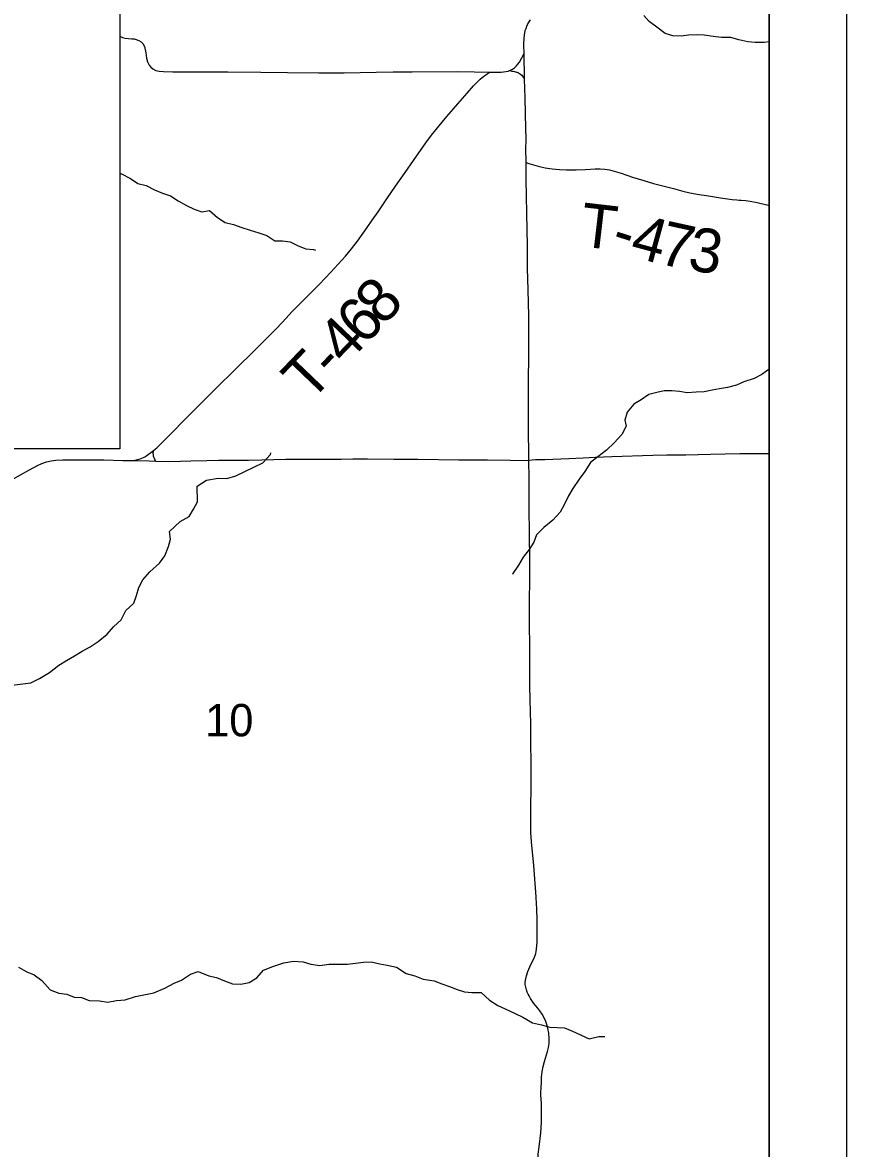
# Model space of a CAD drawing. Extents: x -7.5 to 53.5, y 0 to 22.
# Drawn here: x 7.935 to 9, y 15.27 to 16.725 of the extents above; entities that cross this region are included whole.
import ezdxf

# ---------------------------------------------------------------- set-up
doc = ezdxf.new("R2010")
doc.units = 0
for name, color, linetype in [('GM_X_Corporation', 7, 'Continuous'), ('GM_X_Minor_River', 7, 'Continuous'), ('GM_X_Section_Text', 7, 'Continuous'), ('GM_X_Township_Road', 7, 'Continuous'), ('GM_X_Township_Road_Text', 7, 'Continuous'), ('SH_Data', 7, 'Continuous'), ('SH_Text', 7, 'Continuous')]:
    doc.layers.add(name, color=color, linetype=linetype)

msp = doc.modelspace()

# ---------------------------------------------------------------- linework, layer by layer
at = {"layer": 'GM_X_Corporation'}
msp.add_lwpolyline([(8.9, 14.1), (8.9, 19.1887), (8.5159, 19.1718), (8.414, 19.1709), (7.544, 19.1455), (6.5522, 19.1561), (6.0433, 19.1527), (6.0424, 19.1527), (5.0411, 19.1401), (4.5565, 19.1354), (4.5696, 18.2604), (4.5718, 18.1276), (4.5771, 17.6201), (4.5749, 17.2575), (4.577, 17.1178), (4.5822, 16.8992), (4.5826, 16.8462), (4.5872, 16.3635), (4.5873, 16.3533), (4.594, 15.8096), (4.6021, 15.6139), (4.6087, 14.5302)], dxfattribs=at)
at = {"layer": 'GM_X_Minor_River'}
for points in [[(8.9, 16.7003), (8.8936, 16.6998), (8.8822, 16.6996), (8.8724, 16.7004), (8.861, 16.7032), (8.8504, 16.7059), (8.8387, 16.706), (8.8277, 16.7076), (8.8163, 16.7093), (8.8065, 16.7097), (8.7959, 16.7091), (8.7864, 16.708), (8.7754, 16.7081), (8.7656, 16.7112), (8.755, 16.7193), (8.7452, 16.7266), (8.738, 16.7346)], [(8.061, 16.53), (8.0633, 16.5299), (8.0746, 16.5237), (8.0844, 16.5172), (8.095, 16.5148), (8.1059, 16.5094), (8.1161, 16.5051), (8.1263, 16.5016), (8.1365, 16.4951), (8.1471, 16.4889), (8.1569, 16.4843), (8.1671, 16.4808), (8.1769, 16.4826), (8.1871, 16.4734), (8.1973, 16.4672), (8.2079, 16.4645), (8.2185, 16.4606), (8.2294, 16.4571), (8.2404, 16.4536), (8.251, 16.4501), (8.2615, 16.4435), (8.271, 16.4434), (8.2812, 16.4422), (8.2914, 16.4368), (8.3012, 16.4329), (8.3111, 16.4321), (8.3137, 16.4313)], [(8.9, 16.2775), (8.8908, 16.2706), (8.8805, 16.2654), (8.8672, 16.2613), (8.8577, 16.2569), (8.8463, 16.2539), (8.8361, 16.2521), (8.8266, 16.2503), (8.8159, 16.2481), (8.8057, 16.2478), (8.7943, 16.2468), (8.7841, 16.2488), (8.7743, 16.2496), (8.7644, 16.2494), (8.7549, 16.2472), (8.7446, 16.2446), (8.7347, 16.2379), (8.7252, 16.2323), (8.7168, 16.2221), (8.7137, 16.2115), (8.7155, 16.2038)], [(8.7155, 16.2038), (8.7099, 16.1931), (8.6998, 16.1824), (8.69, 16.1729), (8.6788, 16.164), (8.669, 16.1567), (8.6619, 16.1453), (8.6544, 16.1354), (8.6465, 16.1232), (8.6406, 16.1136), (8.6354, 16.103), (8.6301, 16.0927), (8.6204, 16.0824), (8.6091, 16.0728), (8.5993, 16.0632), (8.596, 16.0537), (8.59, 16.0442), (8.5822, 16.0346), (8.5762, 16.024), (8.5687, 16.0133), (8.5684, 16.0121)], [(7.9217, 15.869), (7.9357, 15.871), (7.9459, 15.8722), (7.9573, 15.8776), (7.9701, 15.8853), (7.9821, 15.8949), (7.9919, 15.9011), (8.0025, 15.9069), (8.0123, 15.913), (8.0228, 15.9184), (8.033, 15.9253), (8.0446, 15.9349), (8.0529, 15.9445), (8.0627, 15.9533), (8.0686, 15.9655), (8.0791, 15.975), (8.0825, 15.9849), (8.0854, 15.9952), (8.0906, 16.0051), (8.0996, 16.0154), (8.1124, 16.0269), (8.1191, 16.0364), (8.1239, 16.0482), (8.1265, 16.0577), (8.1253, 16.0676), (8.1388, 16.0806), (8.1505, 16.0872), (8.1561, 16.0967), (8.1613, 16.1062), (8.1611, 16.1263), (8.1732, 16.134), (8.1879, 16.1368), (8.1993, 16.1361), (8.211, 16.1396), (8.2227, 16.1454), (8.2352, 16.1512), (8.2457, 16.1566), (8.2559, 16.167), (8.2562, 16.1692)], [(7.9299, 15.5045), (7.941, 15.4985), (7.9505, 15.4948), (7.96, 15.4873), (7.9708, 15.4752), (7.9822, 15.4712), (7.9924, 15.4697), (8.0019, 15.466), (8.0114, 15.4653), (8.0213, 15.4616), (8.0349, 15.461), (8.0455, 15.4592), (8.0569, 15.4615), (8.0679, 15.4624), (8.0811, 15.4667), (8.0943, 15.4694), (8.1049, 15.4714), (8.1193, 15.4776), (8.131, 15.4838), (8.1408, 15.488), (8.1521, 15.4957), (8.1623, 15.4992), (8.176, 15.4936), (8.1858, 15.4911), (8.1961, 15.487), (8.2068, 15.4829), (8.2174, 15.4826), (8.2283, 15.4846), (8.2381, 15.4908), (8.2468, 15.5007), (8.2588, 15.5053), (8.2728, 15.5104), (8.2853, 15.5124), (8.2978, 15.5117), (8.3077, 15.5084), (8.3194, 15.5066), (8.3316, 15.5086), (8.3456, 15.5087), (8.3554, 15.5084), (8.3759, 15.5109), (8.3857, 15.5113), (8.3971, 15.5088), (8.4066, 15.5073), (8.4184, 15.5044)], [(8.4184, 15.5044), (8.4309, 15.4965), (8.4423, 15.4932), (8.453, 15.4891), (8.467, 15.487), (8.4773, 15.4829), (8.4868, 15.4796), (8.4967, 15.4758), (8.5062, 15.4729), (8.5157, 15.4718), (8.5278, 15.4719), (8.5389, 15.4618), (8.5495, 15.455), (8.559, 15.4506), (8.572, 15.4446), (8.5819, 15.4398), (8.5941, 15.4326), (8.6058, 15.4301), (8.6165, 15.4271), (8.6263, 15.4265), (8.6358, 15.4262), (8.6461, 15.4217), (8.6674, 15.412), (8.6799, 15.4148), (8.6878, 15.4152)]]:
    msp.add_lwpolyline(points, dxfattribs=at)
at = {"layer": 'GM_X_Township_Road'}
msp.add_line((8.5841, 16.6521), (8.5833, 16.6853), dxfattribs=at)
for points in [[(8.5833, 16.6853), (8.5831, 16.6965), (8.5834, 16.7058), (8.5842, 16.712), (8.5849, 16.715), (8.5859, 16.7179), (8.587, 16.7208), (8.5883, 16.7236), (8.5898, 16.7264), (8.5915, 16.7289)], [(8.061, 16.7079), (8.0644, 16.706), (8.0677, 16.7053), (8.0764, 16.7044), (8.0793, 16.7042), (8.0822, 16.7035), (8.0856, 16.7024), (8.0887, 16.7007), (8.0909, 16.6982), (8.0928, 16.6944), (8.0945, 16.6865), (8.0953, 16.6794), (8.0966, 16.6745), (8.0987, 16.6704), (8.101, 16.6677), (8.1036, 16.6657), (8.1077, 16.6635), (8.1119, 16.6624), (8.1176, 16.6621), (8.1296, 16.6619), (8.134, 16.6619), (8.1421, 16.6616), (8.1603, 16.6616), (8.179, 16.6616), (8.2005, 16.6616), (8.2434, 16.6614), (8.2778, 16.6607), (8.3181, 16.6605), (8.351, 16.6606), (8.3924, 16.6613), (8.4141, 16.6617), (8.4389, 16.6618), (8.4978, 16.6622), (8.5195, 16.6618), (8.5385, 16.6614)], [(8.5645, 16.6633), (8.5657, 16.6637), (8.5684, 16.6653), (8.571, 16.6669), (8.5733, 16.669), (8.5776, 16.6741), (8.5833, 16.6853)], [(8.5385, 16.6614), (8.5473, 16.6612), (8.5536, 16.6613), (8.5597, 16.662), (8.5628, 16.6627), (8.5645, 16.6633)], [(8.5645, 16.6633), (8.5662, 16.663), (8.5677, 16.6628), (8.5694, 16.6625), (8.5709, 16.6623), (8.5724, 16.6619), (8.5735, 16.6615), (8.5745, 16.6611), (8.5761, 16.6604), (8.5776, 16.6595), (8.5788, 16.6587), (8.5804, 16.6575), (8.5841, 16.6521)], [(8.3871, 16.4699), (8.3948, 16.4809), (8.4069, 16.4987), (8.4174, 16.514), (8.4299, 16.5318), (8.4403, 16.5472), (8.4563, 16.57), (8.4638, 16.5798), (8.4715, 16.5895), (8.4835, 16.6038), (8.4977, 16.6202), (8.5097, 16.6343), (8.5179, 16.6436), (8.5222, 16.648), (8.5267, 16.6523), (8.5315, 16.6562), (8.5339, 16.658), (8.5385, 16.6614)], [(8.586, 16.5444), (8.5858, 16.5631), (8.5859, 16.5724), (8.5859, 16.5754), (8.5856, 16.5879), (8.5846, 16.6282), (8.5841, 16.6521)], [(8.5897, 16.1599), (8.5897, 16.1614), (8.5893, 16.2035), (8.5891, 16.2221), (8.5889, 16.2407), (8.5891, 16.2637), (8.5894, 16.2935), (8.5894, 16.3173), (8.5894, 16.3326), (8.5895, 16.3462), (8.5887, 16.3802), (8.588, 16.4081), (8.5878, 16.4243), (8.5876, 16.4375), (8.5873, 16.4577), (8.5869, 16.4794), (8.5865, 16.5011), (8.5862, 16.5228), (8.586, 16.5444)], [(8.586, 16.5444), (8.5897, 16.5433), (8.5927, 16.5424), (8.6016, 16.5399), (8.6106, 16.5378), (8.6198, 16.5362), (8.629, 16.5353), (8.6382, 16.5349), (8.6506, 16.535), (8.6629, 16.5357), (8.6753, 16.5364), (8.6815, 16.5364), (8.6877, 16.536), (8.6938, 16.535), (8.6999, 16.5335), (8.7087, 16.5306), (8.7234, 16.5255), (8.7383, 16.5211), (8.7506, 16.5176), (8.7766, 16.5108), (8.7885, 16.5076), (8.7975, 16.5055), (8.8097, 16.5033), (8.8189, 16.5017), (8.8372, 16.4988), (8.8463, 16.4975), (8.8524, 16.4968), (8.8583, 16.4962), (8.8613, 16.4959), (8.8641, 16.4957), (8.8697, 16.4953), (8.8757, 16.4944), (8.8848, 16.4927), (8.8969, 16.49), (8.9, 16.4891)], [(8.1047, 16.1723), (8.1087, 16.1759), (8.1201, 16.1869), (8.1527, 16.2201), (8.1702, 16.2377), (8.1834, 16.2508), (8.2122, 16.2791), (8.2343, 16.3008), (8.252, 16.3182), (8.2627, 16.3293), (8.2712, 16.3382), (8.2753, 16.3428), (8.2838, 16.3519), (8.2902, 16.3586), (8.3035, 16.3717), (8.3188, 16.3871), (8.3337, 16.4029), (8.3524, 16.4236), (8.3604, 16.4331), (8.368, 16.4429), (8.3806, 16.4606), (8.3871, 16.4699)], [(8.0797, 16.1593), (8.084, 16.1605), (8.0871, 16.1616), (8.0914, 16.1634), (8.0942, 16.1648), (8.0965, 16.1663), (8.1011, 16.1697), (8.1047, 16.1723)], [(8.1075, 16.1587), (8.1064, 16.1606), (8.1057, 16.1621), (8.1051, 16.1636), (8.1047, 16.1651), (8.1043, 16.1669), (8.1041, 16.1688), (8.1041, 16.1699), (8.1043, 16.1708), (8.1045, 16.1716), (8.1047, 16.1723)], [(8.5897, 16.1599), (8.598, 16.1607), (8.6103, 16.1609), (8.6413, 16.1621), (8.6598, 16.163), (8.6753, 16.1637), (8.6968, 16.1647), (8.7496, 16.1665), (8.7679, 16.1668), (8.7925, 16.1669), (8.8244, 16.1678), (8.8624, 16.1683), (8.9, 16.1684)], [(7.9218, 16.1349), (7.9432, 16.147), (7.9545, 16.1531), (7.9602, 16.1555), (7.9661, 16.1575), (7.9721, 16.1589), (7.9782, 16.1598), (7.9873, 16.1603), (8.0153, 16.1604), (8.0405, 16.1602), (8.0648, 16.1596), (8.0797, 16.1593)], [(8.0797, 16.1593), (8.0989, 16.159), (8.1075, 16.1587)], [(8.1075, 16.1587), (8.1237, 16.1582), (8.1392, 16.1584), (8.1526, 16.1588), (8.1733, 16.1595), (8.1888, 16.1597), (8.2043, 16.1597), (8.2272, 16.1598), (8.2446, 16.1602), (8.2601, 16.1607), (8.2755, 16.1612), (8.2942, 16.1613), (8.322, 16.1611), (8.3468, 16.1613), (8.3623, 16.1614), (8.3809, 16.1615), (8.4151, 16.1612), (8.4461, 16.161), (8.4989, 16.1604), (8.5362, 16.1604), (8.5653, 16.1598), (8.5865, 16.1596), (8.5897, 16.1599)], [(8.606, 15.3097), (8.606, 15.3137), (8.6058, 15.3286), (8.6052, 15.3396), (8.6052, 15.3428), (8.6054, 15.3487), (8.6057, 15.3558), (8.6061, 15.3626), (8.6067, 15.3692), (8.6081, 15.3762), (8.6096, 15.3829), (8.6137, 15.3957), (8.6149, 15.4009), (8.6157, 15.4061), (8.6158, 15.4125), (8.6155, 15.4191), (8.6142, 15.4253), (8.6131, 15.4294), (8.6115, 15.4346), (8.6093, 15.4392), (8.6067, 15.4437), (8.6036, 15.448), (8.6011, 15.4515), (8.596, 15.4576), (8.5917, 15.4641), (8.5898, 15.4675), (8.5886, 15.4697), (8.5875, 15.4725), (8.5866, 15.4755), (8.5858, 15.4788), (8.585, 15.4822), (8.5849, 15.4851), (8.5855, 15.4894), (8.5866, 15.4935), (8.5884, 15.4992), (8.5923, 15.508), (8.5964, 15.5163), (8.5985, 15.5222), (8.5992, 15.525), (8.5996, 15.5278), (8.6003, 15.537), (8.6003, 15.5433), (8.6004, 15.5597), (8.6002, 15.5684), (8.6, 15.5772), (8.5998, 15.5809), (8.5996, 15.5859), (8.5991, 15.5956), (8.5958, 15.6358), (8.5931, 15.6667), (8.5923, 15.6791), (8.5919, 15.6915), (8.592, 15.7008), (8.5922, 15.7132), (8.5924, 15.735), (8.5924, 15.7661), (8.5922, 15.7972), (8.5919, 15.819), (8.5913, 15.8501), (8.5909, 15.8687), (8.5907, 15.8904), (8.5906, 15.9183), (8.5905, 15.9493), (8.5904, 15.9711), (8.5908, 16.0115), (8.5908, 16.0332), (8.5904, 16.0612), (8.5901, 16.1017), (8.5898, 16.1359), (8.5897, 16.1599)], [(8.596, 14.9778), (8.5963, 14.9903), (8.5973, 15.0183), (8.5982, 15.0494), (8.6, 15.1084), (8.6007, 15.1364), (8.6005, 15.1551), (8.5994, 15.1893), (8.5992, 15.2079), (8.5994, 15.2307), (8.5998, 15.2411), (8.6005, 15.2483), (8.6007, 15.2511), (8.601, 15.254), (8.6017, 15.2631), (8.6027, 15.2723), (8.6049, 15.2903), (8.6061, 15.3037), (8.606, 15.3097)]]:
    msp.add_lwpolyline(points, dxfattribs=at)
at = {"layer": 'SH_Data'}
for p, q in [((9, 21), (9, 14)), ((8.9, 20.9), (8.9, 14.1))]:
    msp.add_line(p, q, dxfattribs=at)
at = {"layer": 'SH_Text'}
msp.add_lwpolyline([(6.5259, 16.7419), (8.061, 16.7419), (8.061, 16.1744), (6.5259, 16.1744)], close=True, dxfattribs=at)

# ---------------------------------------------------------------- texts
at = {"layer": 'GM_X_Section_Text'}
msp.add_text('10', height=0.04186, rotation=0, dxfattribs=at).set_placement((8.1713, 15.8029))
at = {"layer": 'GM_X_Township_Road_Text'}
for s, rotation, p in [('T', 353.3034, (8.6541, 16.4365)), ('4', 344.6523, (8.7183, 16.4242)), ('7', 347.6128, (8.7551, 16.4142)), ('3', 351.5567, (8.7935, 16.4059)), ('-', 342.1328, (8.6934, 16.4322)), ('8', 46.6959, (8.4012, 16.3322)), ('6', 46.3575, (8.3768, 16.3066)), ('4', 46.2634, (8.3525, 16.2813)), ('T', 46.2274, (8.3069, 16.2337)), ('-', 46.2144, (8.3363, 16.2644))]:
    msp.add_text(s, height=0.0568, rotation=rotation, dxfattribs=at).set_placement(p)

doc.saveas('drawing.dxf')
